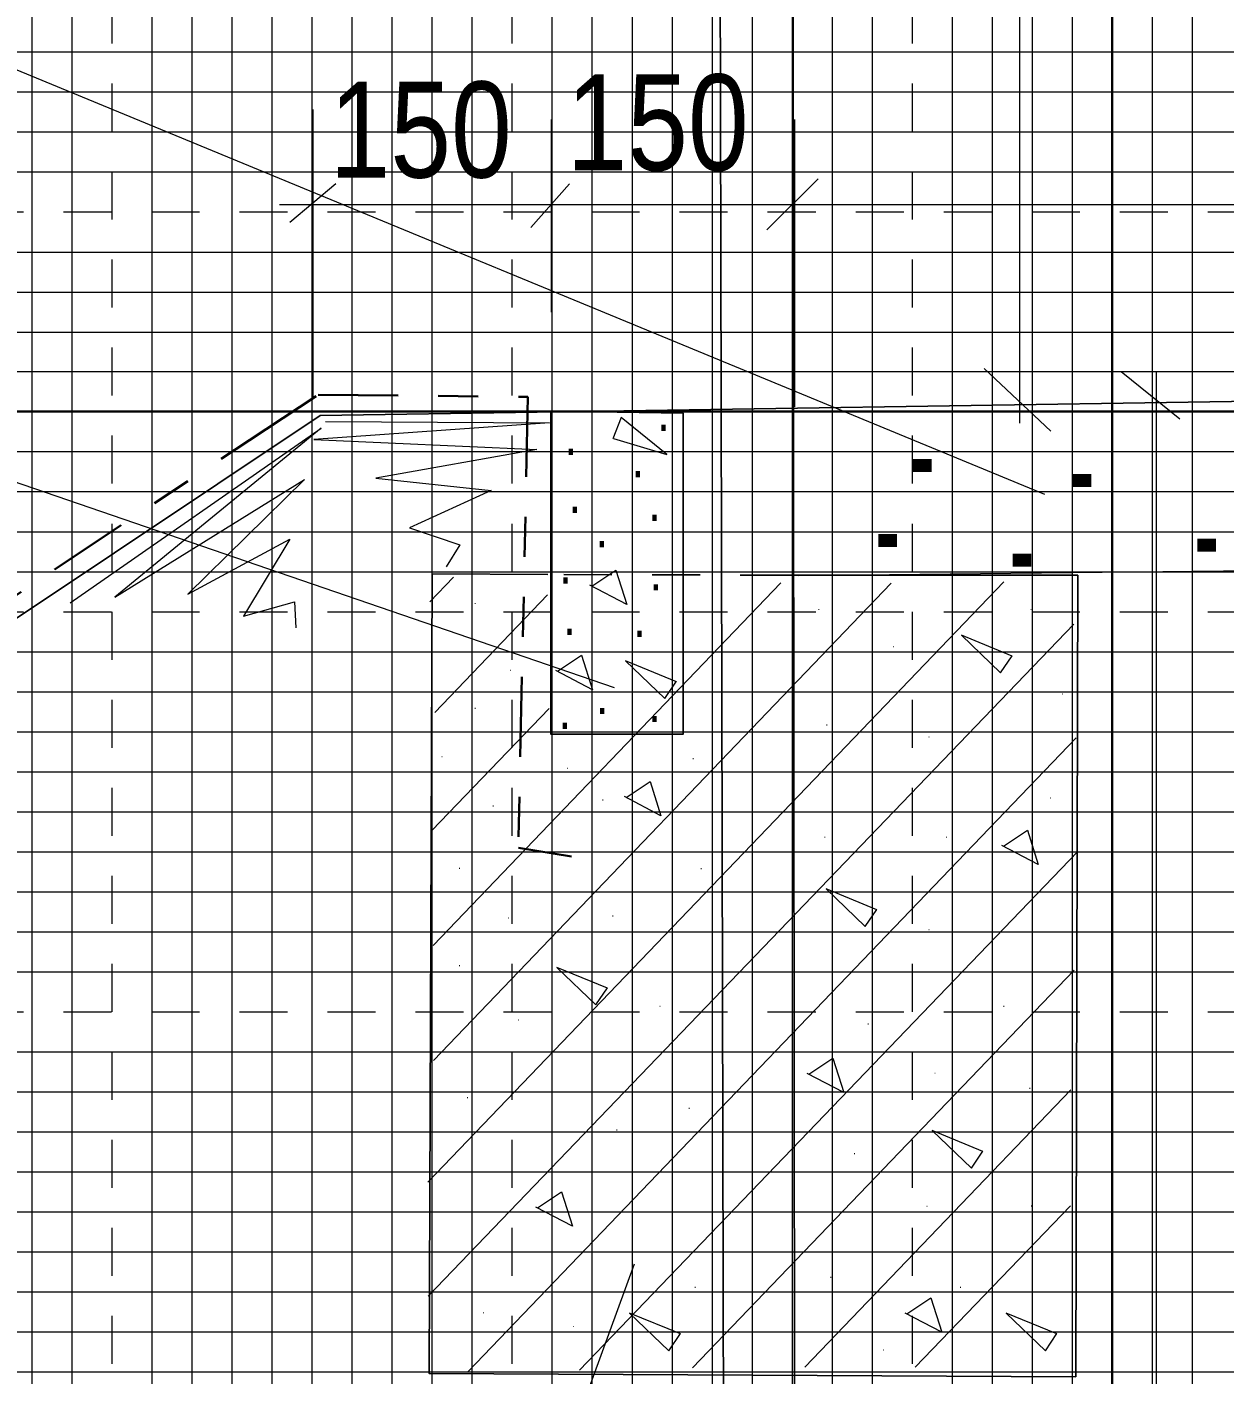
# Model space of a CAD drawing. Extents: x -265.4 to -236, y -5.8 to 40.6.
# Drawn here: x -248.083 to -245.091, y 33.193 to 36.559 of the extents above; entities that cross this region are included whole.
import ezdxf
from ezdxf.enums import TextEntityAlignment as Align

# ---------------------------------------------------------------- set-up
doc = ezdxf.new("R2010")
doc.units = 0
doc.header["$LTSCALE"] = 0.04
doc.linetypes.add('DASH_DOUBLE_DOT', pattern=[9.2, 5, -1.2, 0.3, -1.2, 0.3, -1.2])
doc.linetypes.add('MEDIUM_DASHED', pattern=[4.5, 3, -1.5])
for name, color, linetype, lineweight in [('1', 7, 'Continuous', 13), ('2', 7, 'MEDIUM_DASHED', 13), ('3', 7, 'Continuous', 13), ('4', 7, 'Continuous', 35), ('63', 7, 'Continuous', 13)]:
    doc.layers.add(name, color=color, linetype=linetype, lineweight=lineweight)

msp = doc.modelspace()

# ---------------------------------------------------------------- linework, layer by layer
at = {"layer": '1'}
for p, q in [((-248.071, 40.598), (-248.071, 19.652)), ((-247.971, 40.598), (-247.971, 19.652)), ((-247.771, 40.598), (-247.771, 19.652)), ((-247.671, 40.598), (-247.671, 19.652)), ((-247.571, 40.598), (-247.571, 19.652)), ((-247.471, 40.598), (-247.471, 19.652)), ((-247.271, 40.598), (-247.271, 19.652)), ((-247.171, 40.598), (-247.171, 19.652)), ((-247.071, 40.598), (-247.071, 19.652)), ((-246.971, 40.598), (-246.971, 19.652)), ((-246.771, 40.598), (-246.771, 19.652)), ((-246.671, 40.598), (-246.671, 19.652)), ((-246.571, 40.598), (-246.571, 19.652)), ((-246.471, 40.598), (-246.471, 19.652)), ((-246.271, 40.598), (-246.271, 19.652)), ((-246.171, 40.598), (-246.171, 19.652)), ((-246.071, 40.598), (-246.071, 19.652)), ((-245.971, 40.598), (-245.971, 19.652)), ((-245.771, 40.598), (-245.771, 19.652)), ((-245.671, 40.598), (-245.671, 19.652)), ((-245.571, 40.598), (-245.571, 19.652)), ((-245.471, 40.598), (-245.471, 19.652)), ((-245.271, 40.598), (-245.271, 19.652)), ((-245.171, 40.598), (-245.171, 19.652)), ((-265.372, 36.497), (-236.262, 36.497)), ((-265.372, 36.397), (-236.262, 36.397)), ((-265.372, 36.297), (-236.262, 36.297)), ((-265.372, 36.197), (-236.262, 36.197)), ((-265.372, 35.997), (-236.262, 35.997)), ((-265.372, 35.897), (-236.262, 35.897)), ((-265.372, 35.797), (-236.262, 35.797)), ((-265.372, 35.698), (-236.262, 35.698)), ((-265.372, 35.498), (-236.262, 35.498)), ((-265.372, 35.398), (-236.262, 35.398)), ((-265.372, 35.298), (-236.262, 35.298)), ((-265.372, 35.198), (-236.262, 35.198)), ((-265.372, 34.998), (-236.262, 34.998)), ((-265.372, 34.898), (-236.262, 34.898)), ((-265.372, 34.798), (-236.262, 34.798)), ((-265.372, 34.698), (-236.262, 34.698)), ((-265.372, 34.498), (-236.262, 34.498)), ((-265.372, 34.398), (-236.262, 34.398)), ((-265.372, 34.298), (-236.262, 34.298)), ((-265.372, 34.198), (-236.262, 34.198)), ((-265.372, 33.998), (-236.262, 33.998)), ((-265.372, 33.898), (-236.262, 33.898)), ((-265.372, 33.798), (-236.262, 33.798)), ((-265.372, 33.698), (-236.262, 33.698)), ((-265.372, 33.498), (-236.262, 33.498)), ((-265.372, 33.398), (-236.262, 33.398)), ((-265.372, 33.298), (-236.262, 33.298)), ((-265.372, 33.198), (-236.262, 33.198))]:
    msp.add_line(p, q, dxfattribs=at)
at = {"layer": '2'}
for p, q in [((-247.871, 40.598), (-247.871, 19.652)), ((-246.871, 40.598), (-246.871, 19.652)), ((-245.871, 40.598), (-245.871, 19.652)), ((-265.372, 36.097), (-236.262, 36.097)), ((-265.372, 35.098), (-236.262, 35.098)), ((-265.372, 34.098), (-236.262, 34.098))]:
    msp.add_line(p, q, dxfattribs=at)
at = {"layer": '3'}
for p, q in [((-247.371, 40.598), (-247.371, 19.652)), ((-246.371, 40.598), (-246.371, 19.652)), ((-265.372, 34.598), (-236.262, 34.598)), ((-265.372, 33.598), (-236.262, 33.598))]:
    msp.add_line(p, q, dxfattribs=at)
at = {"layer": '4'}
for p, q in [((-245.371, 40.598), (-245.371, 19.652)), ((-265.372, 35.598), (-236.262, 35.598))]:
    msp.add_line(p, q, dxfattribs=at)
at = {"layer": '63'}
for p, q in [((-245.603, 40.499), (-245.603, 35.569)), ((-247.368, 35.629), (-247.368, 36.353)), ((-246.772, 35.847), (-246.772, 36.328)), ((-246.164, 35.61), (-246.164, 36.328)), ((-247.311, 36.167), (-247.426, 36.071)), ((-246.727, 36.167), (-246.824, 36.058)), ((-246.106, 36.18), (-246.234, 36.052)), ((-247.452, 36.116), (-241.3, 36.116)), ((-245.691, 35.706), (-245.524, 35.549)), ((-245.349, 35.698), (-245.202, 35.58)), ((-245.261, 35.698), (-245.261, 31.562)), ((-241.391, 35.238), (-246.155, 35.188)), ((-245.642, 35.173), (-247.081, 33.672)), ((-247.017, 35.184), (-247.076, 35.123)), ((-246.199, 35.17), (-247.068, 34.264)), ((-245.923, 35.169), (-247.067, 33.976)), ((-246.782, 35.14), (-247.064, 34.846)), ((-245.467, 35.067), (-247.08, 33.387)), ((-246.778, 34.856), (-247.071, 34.551)), ((-245.461, 34.783), (-246.981, 33.198)), ((-245.458, 34.498), (-246.702, 33.202)), ((-245.466, 34.202), (-246.42, 33.208)), ((-245.474, 33.903), (-246.139, 33.21)), ((-245.475, 33.613), (-245.863, 33.21))]:
    msp.add_line(p, q, dxfattribs=at)
at = {"layer": '63', "linetype": 'MEDIUM_DASHED', "lineweight": 25}
msp.add_line((-246.181, 35.189), (-246.781, 35.191), dxfattribs=at)
at = {"layer": '63', "lineweight": 25}
for points in [[(-246.172, 39.471), (-246.163, 31.586), (-246.339, 31.586), (-246.359, 40.381), (-246.182, 40.381)], [(-246.774, 35.599), (-246.774, 34.792), (-246.443, 34.792), (-246.443, 35.594)]]:
    msp.add_lwpolyline(points, close=True, dxfattribs=at)
at = {"layer": '63'}
for points in [[(-245.539, 35.391), (-248.28, 36.522), (-254.169, 36.522)], [(-247.975, 35.12), (-247.348, 35.557), (-247.863, 35.134), (-247.389, 35.428), (-247.681, 35.142), (-247.426, 35.279), (-247.542, 35.087), (-247.414, 35.123), (-247.411, 35.058)], [(-247.337, 35.573), (-246.777, 35.57), (-247.366, 35.528), (-246.809, 35.503), (-247.211, 35.432), (-246.923, 35.401), (-247.127, 35.308), (-247.001, 35.265), (-247.035, 35.21)], [(-246.617, 35.531), (-246.484, 35.491), (-246.598, 35.583), (-246.619, 35.53)], [(-246.615, 34.908), (-248.428, 35.53), (-254.569, 35.53)], [(-246.671, 35.162), (-246.611, 35.202), (-246.584, 35.116), (-246.676, 35.164)], [(-245.621, 34.987), (-245.748, 35.039), (-245.65, 34.945), (-245.621, 34.988)], [(-246.757, 34.949), (-246.697, 34.989), (-246.67, 34.903), (-246.761, 34.951)], [(-246.46, 34.923), (-246.587, 34.975), (-246.489, 34.881), (-246.46, 34.924)], [(-246.586, 34.634), (-246.526, 34.674), (-246.499, 34.588), (-246.59, 34.636)], [(-245.643, 34.512), (-245.583, 34.552), (-245.556, 34.466), (-245.647, 34.514)], [(-245.959, 34.353), (-246.086, 34.405), (-245.988, 34.311), (-245.959, 34.354)], [(-246.632, 34.157), (-246.759, 34.209), (-246.661, 34.115), (-246.632, 34.158)], [(-246.129, 33.942), (-246.069, 33.982), (-246.042, 33.896), (-246.133, 33.944)], [(-245.694, 33.749), (-245.821, 33.801), (-245.723, 33.707), (-245.694, 33.75)], [(-246.807, 33.608), (-246.747, 33.648), (-246.72, 33.562), (-246.811, 33.61)], [(-246.566, 33.467), (-247.017, 32.23), (-251.552, 32.23)], [(-245.884, 33.343), (-245.824, 33.383), (-245.797, 33.297), (-245.888, 33.345)], [(-246.45, 33.293), (-246.577, 33.345), (-246.479, 33.251), (-246.45, 33.294)], [(-245.509, 33.293), (-245.636, 33.345), (-245.538, 33.251), (-245.509, 33.294)]]:
    msp.add_lwpolyline(points, dxfattribs=at)
at = {"layer": '63', "lineweight": 25}
for points in [[(-241.385, 35.68), (-247.35, 35.588), (-252.736, 31.992)], [(-246.181, 35.189), (-245.457, 35.189), (-245.462, 33.186), (-247.078, 33.194), (-247.07, 35.193), (-246.781, 35.191)]]:
    msp.add_lwpolyline(points, dxfattribs=at)
at = {"layer": '63', "linetype": 'DASH_DOUBLE_DOT', "lineweight": 35}
msp.add_lwpolyline([(-252.677, 32.102), (-247.527, 35.527), (-247.355, 35.64), (-246.831, 35.635), (-246.855, 34.508), (-246.722, 34.486)], dxfattribs=at)

# ---------------------------------------------------------------- texts
at = {"layer": '63'}
for s, height, width, p in [('150', 0.24, 0.85, (-246.507, 36.201)), ('150', 0.24, 0.85, (-247.099, 36.183)), ('.', 0.1, 0.85, (-246.4925, 35.55)), ('.', 0.1, 0.85, (-246.7235, 35.49)), ('.', 0.1, 0.85, (-246.5565, 35.434)), ('.', 0.1, 0.85, (-246.7135, 35.345)), ('.', 0.1, 0.85, (-246.5145, 35.325)), ('.', 0.1, 0.85, (-246.6465, 35.259)), ('.', 0.1, 0.85, (-246.7375, 35.168)), ('.', 0.1, 0.85, (-246.5115, 35.151)), ('.', 0.02, 0.8, (-246.963, 35.117)), ('.', 0.02, 0.8, (-246.104, 35.102)), ('.', 0.02, 0.8, (-245.574, 35.102)), ('.', 0.1, 0.85, (-246.7275, 35.04)), ('.', 0.1, 0.85, (-246.5525, 35.035)), ('.', 0.02, 0.8, (-245.917, 35.009)), ('.', 0.02, 0.8, (-246.874, 34.95)), ('.', 0.02, 0.8, (-245.495, 34.891)), ('.', 0.02, 0.8, (-246.963, 34.855)), ('.', 0.1, 0.85, (-246.6455, 34.842)), ('.', 0.1, 0.85, (-246.7385, 34.805)), ('.', 0.1, 0.85, (-246.5145, 34.822)), ('.', 0.02, 0.8, (-246.084, 34.813)), ('.', 0.02, 0.8, (-245.829, 34.783)), ('.', 0.02, 0.8, (-247.046, 34.734)), ('.', 0.02, 0.8, (-246.418, 34.729)), ('.', 0.02, 0.8, (-246.732, 34.705)), ('.', 0.02, 0.8, (-246.918, 34.611)), ('.', 0.02, 0.8, (-246.644, 34.626)), ('.', 0.02, 0.8, (-245.525, 34.631)), ('.', 0.02, 0.8, (-246.089, 34.533)), ('.', 0.02, 0.8, (-245.785, 34.533)), ('.', 0.02, 0.8, (-247.002, 34.455)), ('.', 0.02, 0.8, (-246.398, 34.454)), ('.', 0.02, 0.8, (-246.879, 34.331)), ('.', 0.02, 0.8, (-246.619, 34.336)), ('.', 0.02, 0.8, (-245.829, 34.302)), ('.', 0.02, 0.8, (-247.002, 34.212)), ('.', 0.02, 0.8, (-246.501, 34.11)), ('.', 0.02, 0.8, (-245.642, 34.11)), ('.', 0.02, 0.8, (-246.855, 34.076)), ('.', 0.02, 0.8, (-245.981, 34.066)), ('.', 0.02, 0.8, (-245.814, 33.943)), ('.', 0.02, 0.8, (-245.577, 33.905)), ('.', 0.02, 0.8, (-246.982, 33.882)), ('.', 0.02, 0.8, (-246.428, 33.855)), ('.', 0.02, 0.8, (-246.771, 33.831)), ('.', 0.02, 0.8, (-246.609, 33.801)), ('.', 0.02, 0.8, (-246.015, 33.742)), ('.', 0.02, 0.8, (-246.97, 33.627)), ('.', 0.02, 0.8, (-245.834, 33.61)), ('.', 0.02, 0.8, (-245.573, 33.611)), ('.', 0.02, 0.8, (-246.57, 33.511)), ('.', 0.02, 0.8, (-246.074, 33.433)), ('.', 0.02, 0.8, (-246.413, 33.408)), ('.', 0.02, 0.8, (-245.75, 33.408)), ('.', 0.02, 0.8, (-246.942, 33.344)), ('.', 0.02, 0.8, (-246.717, 33.31)), ('.', 0.02, 0.8, (-245.942, 33.251))]:
    msp.add_text(s, height=height, dxfattribs=dict(at, width=width)).set_placement(p, align=Align.CENTER)
at = {"layer": '63', "width": 0.85}
for p in [(-245.822, 35.463), (-245.423, 35.426), (-245.909, 35.276), (-245.112, 35.264), (-245.573, 35.227)]:
    msp.add_text('.', height=0.3, rotation=90, dxfattribs=at).set_placement(p, align=Align.CENTER)

doc.saveas('drawing.dxf')
